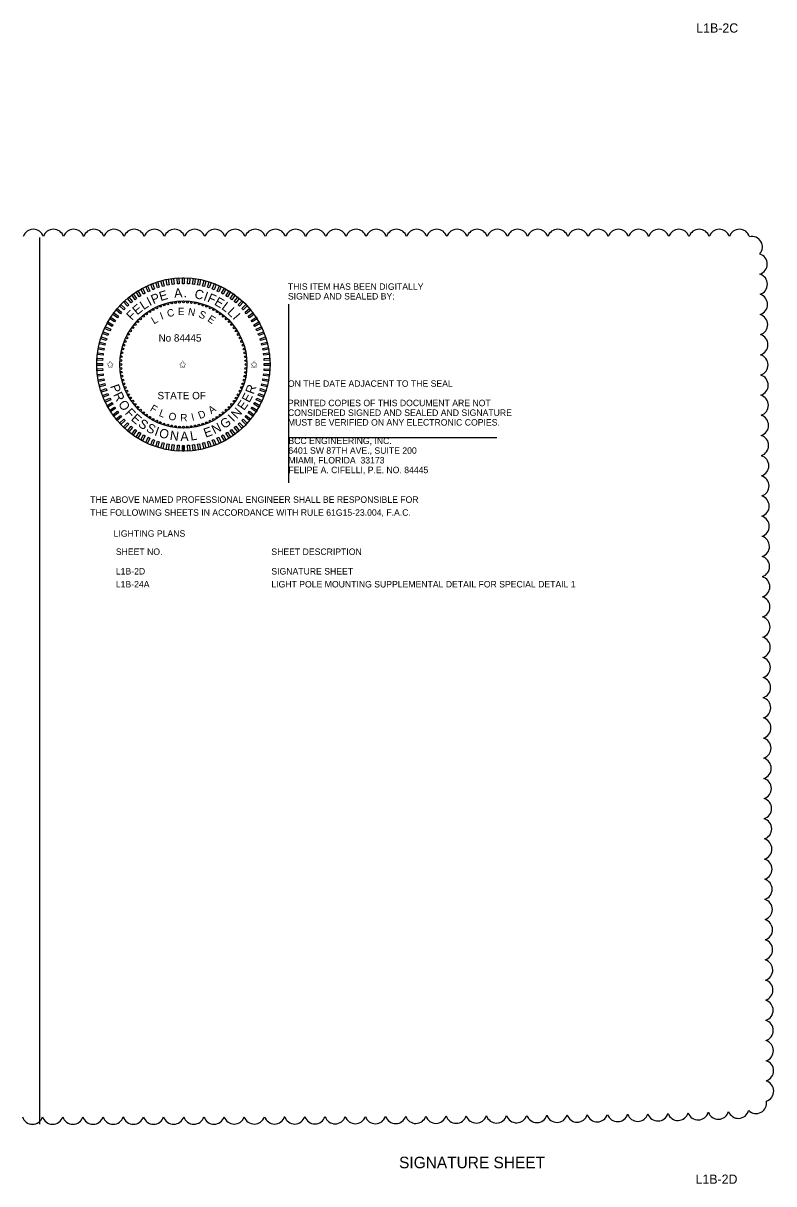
# Model space of a CAD drawing. Extents: x -811.2 to -795, y -2295.2 to -2235.1.
# Drawn here: x -803.27 to -795.14, y -2295.15 to -2282.59 of the extents above; entities that cross this region are included whole.
import ezdxf

# ---------------------------------------------------------------- set-up
doc = ezdxf.new("R2010")
doc.units = 0
for name, color, linetype in [('AdhocPoint_dp', 7, 'Continuous'), ('Cloud_dp', 7, 'Continuous'), ('PlotBorder_dp', 7, 'Continuous'), ('SheetLines_dp', 7, 'Continuous'), ('TextMinor', 7, 'Continuous'), ('TextMisc', 7, 'Continuous'), ('TextNotes', 7, 'Continuous'), ('TextShtNo', 7, 'Continuous')]:
    doc.layers.add(name, color=color, linetype=linetype)

msp = doc.modelspace()

# ---------------------------------------------------------------- linework, layer by layer
at = {"layer": 'AdhocPoint_dp'}
for p, q in [((-800.397, -2285.629), (-800.397, -2287.564)), ((-800.397, -2287.074), (-798.141, -2287.074))]:
    msp.add_line(p, q, dxfattribs=at)
at = {"layer": 'Cloud_dp'}
for centre, start, end in [((-803.157, -2284.933), 17.5, 162.5), ((-802.939, -2284.933), 17.5, 162.5), ((-802.721, -2284.933), 17.5, 162.5), ((-802.502, -2284.933), 17.5, 162.5), ((-802.284, -2284.933), 17.5, 162.5), ((-802.066, -2284.933), 17.5, 162.5), ((-801.847, -2284.933), 17.5, 162.5), ((-801.629, -2284.933), 17.5, 162.5), ((-801.411, -2284.933), 17.5, 162.5), ((-801.192, -2284.933), 17.5, 162.5), ((-800.974, -2284.933), 17.5, 162.5), ((-800.756, -2284.933), 17.5, 162.5), ((-800.537, -2284.933), 17.5, 162.5), ((-800.319, -2284.933), 17.5, 162.5), ((-800.101, -2284.933), 17.5, 162.5), ((-799.882, -2284.933), 17.5, 162.5), ((-799.664, -2284.933), 17.5, 162.5), ((-799.446, -2284.933), 17.5, 162.5), ((-799.227, -2284.933), 17.5, 162.5), ((-799.009, -2284.933), 17.5, 162.5), ((-798.791, -2284.933), 17.5, 162.5), ((-798.572, -2284.933), 17.5, 162.5), ((-798.354, -2284.933), 17.5, 162.5), ((-798.136, -2284.933), 17.5, 162.5), ((-797.917, -2284.933), 17.5, 162.5), ((-797.699, -2284.933), 17.5, 162.5), ((-797.481, -2284.933), 17.5, 162.5), ((-797.262, -2284.933), 17.5, 162.5), ((-797.044, -2284.933), 17.5, 162.5), ((-796.826, -2284.933), 17.5, 162.5), ((-796.607, -2284.933), 17.5, 162.5), ((-796.389, -2284.933), 17.5, 162.5), ((-796.171, -2284.933), 17.5, 162.5), ((-795.952, -2284.933), 17.5, 162.5), ((-795.734, -2284.933), 17.5, 162.5), ((-795.516, -2284.933), 17.5, 162.5), ((-795.381, -2285.01), 318.1116, 103.1116), ((-795.329, -2285.196), 287.9529, 72.9529), ((-795.327, -2285.414), 287.9529, 72.9529), ((-795.326, -2285.632), 287.9529, 72.9529), ((-795.324, -2285.851), 287.9529, 72.9529), ((-795.322, -2286.069), 287.9529, 72.9529), ((-795.32, -2286.287), 287.9529, 72.9529), ((-795.319, -2286.506), 287.9529, 72.9529), ((-795.317, -2286.724), 287.9529, 72.9529), ((-795.315, -2286.942), 287.9529, 72.9529), ((-795.314, -2287.16), 287.9529, 72.9529), ((-795.312, -2287.379), 287.9529, 72.9529), ((-795.31, -2287.597), 287.9529, 72.9529), ((-795.308, -2287.815), 287.9529, 72.9529), ((-795.307, -2288.034), 287.9529, 72.9529), ((-795.305, -2288.252), 287.9529, 72.9529), ((-795.303, -2288.47), 287.9529, 72.9529), ((-795.301, -2288.689), 287.9529, 72.9529), ((-795.3, -2288.907), 287.9529, 72.9529), ((-795.298, -2289.125), 287.9529, 72.9529), ((-795.296, -2289.344), 287.9529, 72.9529), ((-795.295, -2289.562), 287.9529, 72.9529), ((-795.293, -2289.78), 287.9527, 72.9527), ((-795.291, -2289.999), 287.9524, 72.9524), ((-795.289, -2290.217), 287.9521, 72.9521), ((-795.288, -2290.435), 287.9519, 72.9519), ((-795.286, -2290.654), 287.9515, 72.9515), ((-795.284, -2290.872), 287.9512, 72.9512), ((-795.282, -2291.09), 287.9508, 72.9508), ((-795.281, -2291.309), 287.9504, 72.9504), ((-795.279, -2291.527), 287.9499, 72.9499), ((-795.277, -2291.745), 287.9494, 72.9494), ((-795.276, -2291.963), 287.9488, 72.9488), ((-795.274, -2292.182), 287.9481, 72.9481), ((-795.272, -2292.4), 287.9473, 72.9473), ((-795.271, -2292.618), 287.9464, 72.9464), ((-795.269, -2292.837), 287.9452, 72.9452), ((-795.267, -2293.055), 287.9438, 72.9438), ((-795.265, -2293.273), 287.9419, 72.9419), ((-795.264, -2293.492), 287.9394, 72.9394), ((-795.262, -2293.71), 287.9355, 72.9355), ((-795.26, -2293.928), 287.9288, 72.9288), ((-795.259, -2294.147), 287.9106, 72.9106), ((-795.336, -2294.276), 225.4798, 10.4798), ((-803.166, -2294.393), 197.496, 342.496), ((-802.948, -2294.393), 197.5011, 342.5011), ((-802.729, -2294.393), 197.5111, 342.5111), ((-802.511, -2294.393), 197.522, 342.522), ((-802.293, -2294.393), 197.5335, 342.5335), ((-802.074, -2294.393), 197.5456, 342.5456), ((-801.856, -2294.393), 197.5582, 342.5582), ((-801.638, -2294.392), 197.5715, 342.5715), ((-801.42, -2294.392), 197.5855, 342.5855), ((-801.201, -2294.392), 197.6002, 342.6002), ((-800.983, -2294.391), 197.6157, 342.6157), ((-800.765, -2294.391), 197.6322, 342.6322), ((-800.546, -2294.39), 197.6497, 342.6497), ((-800.328, -2294.39), 197.6683, 342.6683), ((-800.11, -2294.389), 197.6881, 342.6881), ((-799.891, -2294.388), 197.7093, 342.7093), ((-799.673, -2294.387), 197.732, 342.732), ((-799.455, -2294.387), 197.7565, 342.7565), ((-799.236, -2294.386), 197.7829, 342.7829), ((-799.018, -2294.384), 197.8116, 342.8116), ((-798.8, -2294.383), 197.8429, 342.8429), ((-798.582, -2294.382), 197.8771, 342.8771), ((-798.363, -2294.38), 197.9149, 342.9149), ((-798.145, -2294.379), 197.9569, 342.9569), ((-797.927, -2294.377), 198.0039, 343.0039), ((-797.708, -2294.375), 198.0569, 343.0569), ((-797.49, -2294.373), 198.1174, 343.1174), ((-797.272, -2294.37), 198.1874, 343.1874), ((-797.054, -2294.367), 198.2696, 343.2696), ((-796.835, -2294.364), 198.368, 343.368), ((-796.617, -2294.361), 198.4888, 343.4888), ((-796.399, -2294.357), 198.642, 343.642), ((-796.181, -2294.352), 198.8454, 343.8454), ((-795.963, -2294.346), 199.1345, 344.1345), ((-795.745, -2294.339), 199.5943, 344.5943), ((-795.527, -2294.329), 200.5167, 345.5167)]:
    msp.add_arc(centre, 0.114, start, end, dxfattribs=at)
at = {"layer": 'TextMinor'}
for radius in [0.938, 0.688]:
    msp.add_circle((-801.533, -2286.283), radius, dxfattribs=at)
at = {"layer": 'TextNotes'}
msp.add_line((-803.086, -2294.507), (-803.086, -2284.907), dxfattribs=at)
at = {"layer": 'TextShtNo'}
for p, q in [((-801.543, -2287.22), (-801.543, -2287.158)), ((-801.533, -2287.22), (-801.533, -2287.158)), ((-801.523, -2287.22), (-801.523, -2287.158))]:
    msp.add_line(p, q, dxfattribs=at)
for points in [[(-801.794, -2285.447), (-801.813, -2285.454), (-801.832, -2285.394), (-801.813, -2285.388)], [(-801.741, -2285.433), (-801.76, -2285.438), (-801.776, -2285.377), (-801.756, -2285.372)], [(-801.687, -2285.421), (-801.707, -2285.425), (-801.718, -2285.364), (-801.699, -2285.36)], [(-801.632, -2285.413), (-801.653, -2285.416), (-801.66, -2285.354), (-801.64, -2285.351)], [(-801.578, -2285.409), (-801.598, -2285.41), (-801.602, -2285.348), (-801.582, -2285.346)], [(-801.523, -2285.408), (-801.543, -2285.408), (-801.543, -2285.345), (-801.523, -2285.345)], [(-801.468, -2285.41), (-801.488, -2285.409), (-801.484, -2285.346), (-801.464, -2285.348)], [(-801.413, -2285.416), (-801.433, -2285.413), (-801.425, -2285.351), (-801.405, -2285.354)], [(-801.359, -2285.425), (-801.379, -2285.421), (-801.367, -2285.36), (-801.347, -2285.364)], [(-801.305, -2285.438), (-801.325, -2285.433), (-801.309, -2285.372), (-801.29, -2285.377)], [(-801.253, -2285.454), (-801.272, -2285.447), (-801.253, -2285.388), (-801.234, -2285.394)], [(-802.039, -2285.569), (-802.055, -2285.581), (-802.092, -2285.53), (-802.076, -2285.518)], [(-801.993, -2285.538), (-802.01, -2285.549), (-802.044, -2285.497), (-802.027, -2285.486)], [(-801.946, -2285.511), (-801.963, -2285.521), (-801.993, -2285.466), (-801.976, -2285.456)], [(-801.896, -2285.487), (-801.915, -2285.495), (-801.941, -2285.439), (-801.923, -2285.43)], [(-801.846, -2285.465), (-801.864, -2285.473), (-801.887, -2285.415), (-801.869, -2285.407)], [(-801.201, -2285.473), (-801.22, -2285.465), (-801.197, -2285.407), (-801.178, -2285.415)], [(-801.151, -2285.495), (-801.169, -2285.487), (-801.143, -2285.43), (-801.125, -2285.439)], [(-801.102, -2285.521), (-801.12, -2285.511), (-801.09, -2285.456), (-801.072, -2285.466)], [(-801.055, -2285.549), (-801.073, -2285.539), (-801.039, -2285.486), (-801.022, -2285.497)], [(-801.01, -2285.581), (-801.027, -2285.569), (-800.99, -2285.518), (-800.974, -2285.53)], [(-802.164, -2285.676), (-802.178, -2285.691), (-802.223, -2285.648), (-802.209, -2285.634)], [(-802.124, -2285.638), (-802.139, -2285.652), (-802.182, -2285.606), (-802.167, -2285.592)], [(-802.083, -2285.602), (-802.098, -2285.615), (-802.138, -2285.567), (-802.123, -2285.554)], [(-800.967, -2285.615), (-800.983, -2285.602), (-800.943, -2285.554), (-800.928, -2285.567)], [(-800.926, -2285.652), (-800.941, -2285.638), (-800.898, -2285.592), (-800.884, -2285.606)], [(-800.888, -2285.691), (-800.902, -2285.676), (-800.856, -2285.634), (-800.843, -2285.648)], [(-802.266, -2285.805), (-802.277, -2285.822), (-802.33, -2285.789), (-802.319, -2285.772)], [(-802.235, -2285.76), (-802.247, -2285.776), (-802.297, -2285.74), (-802.285, -2285.723)], [(-802.201, -2285.717), (-802.214, -2285.733), (-802.262, -2285.693), (-802.249, -2285.677)], [(-800.852, -2285.733), (-800.865, -2285.717), (-800.817, -2285.677), (-800.804, -2285.693)], [(-800.819, -2285.777), (-800.831, -2285.76), (-800.78, -2285.724), (-800.769, -2285.74)], [(-800.789, -2285.822), (-800.799, -2285.805), (-800.747, -2285.772), (-800.736, -2285.789)], [(-802.32, -2285.901), (-802.329, -2285.919), (-802.385, -2285.893), (-802.377, -2285.874)], [(-802.295, -2285.852), (-802.305, -2285.87), (-802.359, -2285.84), (-802.35, -2285.822)], [(-800.761, -2285.87), (-800.771, -2285.852), (-800.716, -2285.822), (-800.707, -2285.84)], [(-800.737, -2285.919), (-800.745, -2285.901), (-800.689, -2285.875), (-800.68, -2285.893)], [(-802.362, -2286.003), (-802.368, -2286.022), (-802.428, -2286.003), (-802.421, -2285.983)], [(-802.343, -2285.951), (-802.35, -2285.97), (-802.408, -2285.947), (-802.401, -2285.928)], [(-800.716, -2285.97), (-800.723, -2285.951), (-800.665, -2285.928), (-800.658, -2285.947)], [(-800.698, -2286.022), (-800.704, -2286.003), (-800.644, -2285.984), (-800.638, -2286.003)], [(-802.4, -2286.163), (-802.402, -2286.183), (-802.464, -2286.175), (-802.462, -2286.155)], [(-802.391, -2286.109), (-802.394, -2286.129), (-802.456, -2286.117), (-802.452, -2286.097)], [(-802.378, -2286.055), (-802.383, -2286.075), (-802.443, -2286.059), (-802.438, -2286.04)], [(-800.683, -2286.075), (-800.688, -2286.055), (-800.627, -2286.04), (-800.622, -2286.059)], [(-800.671, -2286.129), (-800.675, -2286.109), (-800.614, -2286.097), (-800.61, -2286.117)], [(-800.664, -2286.183), (-800.666, -2286.163), (-800.604, -2286.155), (-800.602, -2286.175)], [(-802.408, -2286.273), (-802.408, -2286.293), (-802.47, -2286.293), (-802.47, -2286.273)], [(-802.406, -2286.218), (-802.407, -2286.238), (-802.469, -2286.234), (-802.468, -2286.214)], [(-800.659, -2286.238), (-800.66, -2286.218), (-800.598, -2286.214), (-800.597, -2286.234)], [(-800.658, -2286.293), (-800.658, -2286.273), (-800.595, -2286.273), (-800.595, -2286.293)], [(-802.407, -2286.327), (-802.406, -2286.348), (-802.468, -2286.352), (-802.469, -2286.331)], [(-802.402, -2286.382), (-802.4, -2286.402), (-802.462, -2286.41), (-802.464, -2286.39)], [(-800.666, -2286.402), (-800.664, -2286.382), (-800.602, -2286.39), (-800.604, -2286.41)], [(-800.66, -2286.348), (-800.659, -2286.328), (-800.597, -2286.332), (-800.598, -2286.352)], [(-802.394, -2286.437), (-802.391, -2286.456), (-802.452, -2286.468), (-802.456, -2286.448)], [(-802.383, -2286.49), (-802.378, -2286.51), (-802.438, -2286.526), (-802.443, -2286.506)], [(-800.688, -2286.51), (-800.683, -2286.491), (-800.622, -2286.506), (-800.627, -2286.526)], [(-800.675, -2286.457), (-800.672, -2286.437), (-800.61, -2286.449), (-800.614, -2286.468)], [(-802.368, -2286.543), (-802.362, -2286.563), (-802.421, -2286.582), (-802.428, -2286.563)], [(-802.35, -2286.595), (-802.343, -2286.614), (-802.401, -2286.637), (-802.408, -2286.618)], [(-802.329, -2286.646), (-802.32, -2286.664), (-802.377, -2286.691), (-802.386, -2286.673)], [(-800.746, -2286.664), (-800.737, -2286.646), (-800.68, -2286.673), (-800.689, -2286.691)], [(-800.723, -2286.614), (-800.716, -2286.596), (-800.658, -2286.619), (-800.665, -2286.637)], [(-800.704, -2286.563), (-800.698, -2286.544), (-800.638, -2286.563), (-800.644, -2286.582)], [(-802.305, -2286.695), (-802.295, -2286.713), (-802.35, -2286.743), (-802.359, -2286.725)], [(-802.277, -2286.743), (-802.266, -2286.76), (-802.319, -2286.793), (-802.33, -2286.776)], [(-800.8, -2286.76), (-800.789, -2286.743), (-800.736, -2286.777), (-800.747, -2286.794)], [(-800.771, -2286.713), (-800.761, -2286.695), (-800.707, -2286.726), (-800.716, -2286.743)], [(-802.247, -2286.789), (-802.235, -2286.805), (-802.285, -2286.842), (-802.297, -2286.826)], [(-802.214, -2286.833), (-802.201, -2286.848), (-802.249, -2286.888), (-802.262, -2286.872)], [(-802.178, -2286.874), (-802.164, -2286.889), (-802.209, -2286.932), (-802.223, -2286.917)], [(-800.902, -2286.889), (-800.888, -2286.874), (-800.843, -2286.917), (-800.857, -2286.932)], [(-800.865, -2286.848), (-800.852, -2286.833), (-800.804, -2286.873), (-800.817, -2286.888)], [(-800.831, -2286.805), (-800.819, -2286.789), (-800.769, -2286.826), (-800.78, -2286.842)], [(-802.139, -2286.914), (-802.125, -2286.927), (-802.167, -2286.973), (-802.182, -2286.959)], [(-802.099, -2286.95), (-802.083, -2286.963), (-802.123, -2287.011), (-802.138, -2286.999)], [(-802.055, -2286.985), (-802.039, -2286.997), (-802.076, -2287.047), (-802.092, -2287.035)], [(-802.01, -2287.016), (-801.993, -2287.027), (-802.027, -2287.08), (-802.044, -2287.069)], [(-801.073, -2287.027), (-801.056, -2287.016), (-801.022, -2287.069), (-801.039, -2287.08)], [(-801.027, -2286.997), (-801.011, -2286.985), (-800.974, -2287.035), (-800.99, -2287.047)], [(-800.983, -2286.963), (-800.967, -2286.951), (-800.928, -2286.999), (-800.943, -2287.012)], [(-800.941, -2286.928), (-800.927, -2286.914), (-800.884, -2286.959), (-800.899, -2286.973)], [(-801.963, -2287.045), (-801.946, -2287.054), (-801.976, -2287.109), (-801.993, -2287.099)], [(-801.915, -2287.07), (-801.896, -2287.079), (-801.923, -2287.135), (-801.941, -2287.127)], [(-801.865, -2287.093), (-801.846, -2287.1), (-801.869, -2287.158), (-801.887, -2287.151)], [(-801.813, -2287.112), (-801.794, -2287.118), (-801.813, -2287.177), (-801.832, -2287.171)], [(-801.76, -2287.128), (-801.741, -2287.133), (-801.756, -2287.193), (-801.776, -2287.188)], [(-801.707, -2287.14), (-801.687, -2287.144), (-801.699, -2287.205), (-801.719, -2287.202)], [(-801.653, -2287.15), (-801.633, -2287.152), (-801.64, -2287.214), (-801.661, -2287.212)], [(-801.598, -2287.155), (-801.578, -2287.157), (-801.582, -2287.219), (-801.602, -2287.218)], [(-801.543, -2287.158), (-801.523, -2287.158), (-801.523, -2287.22), (-801.543, -2287.22)], [(-801.488, -2287.157), (-801.468, -2287.155), (-801.464, -2287.218), (-801.484, -2287.219)], [(-801.433, -2287.152), (-801.413, -2287.15), (-801.406, -2287.212), (-801.426, -2287.214)], [(-801.379, -2287.144), (-801.359, -2287.14), (-801.347, -2287.202), (-801.367, -2287.205)], [(-801.325, -2287.133), (-801.306, -2287.128), (-801.29, -2287.188), (-801.31, -2287.193)], [(-801.272, -2287.118), (-801.253, -2287.112), (-801.234, -2287.171), (-801.253, -2287.177)], [(-801.22, -2287.1), (-801.202, -2287.093), (-801.179, -2287.151), (-801.197, -2287.158)], [(-801.17, -2287.079), (-801.151, -2287.07), (-801.125, -2287.127), (-801.143, -2287.135)], [(-801.12, -2287.054), (-801.103, -2287.045), (-801.073, -2287.099), (-801.09, -2287.109)]]:
    msp.add_lwpolyline(points, close=True, dxfattribs=at)
for centre in [(-801.782, -2285.653), (-801.742, -2285.638), (-801.701, -2285.626), (-801.659, -2285.617), (-801.617, -2285.611), (-801.575, -2285.607), (-801.532, -2285.605), (-801.49, -2285.607), (-801.447, -2285.611), (-801.405, -2285.617), (-801.364, -2285.627), (-801.323, -2285.639), (-801.283, -2285.653), (-801.996, -2285.788), (-801.964, -2285.76), (-801.931, -2285.734), (-801.895, -2285.71), (-801.859, -2285.689), (-801.821, -2285.669), (-801.244, -2285.67), (-801.206, -2285.689), (-801.169, -2285.711), (-801.134, -2285.735), (-801.101, -2285.761), (-801.069, -2285.789), (-802.081, -2285.884), (-802.055, -2285.85), (-802.026, -2285.819), (-801.039, -2285.819), (-801.011, -2285.851), (-800.985, -2285.885), (-802.163, -2286.033), (-802.146, -2285.994), (-802.126, -2285.956), (-802.105, -2285.919), (-800.961, -2285.92), (-800.939, -2285.957), (-800.92, -2285.995), (-800.903, -2286.034), (-802.198, -2286.155), (-802.189, -2286.114), (-802.177, -2286.073), (-800.888, -2286.074), (-800.877, -2286.115), (-800.867, -2286.156), (-802.21, -2286.282), (-802.209, -2286.24), (-802.205, -2286.197), (-800.861, -2286.198), (-800.857, -2286.241), (-800.855, -2286.283), (-802.209, -2286.325), (-802.205, -2286.367), (-802.198, -2286.409), (-800.868, -2286.41), (-800.861, -2286.368), (-800.857, -2286.326), (-802.189, -2286.451), (-802.177, -2286.492), (-802.163, -2286.532), (-800.903, -2286.533), (-800.889, -2286.493), (-800.877, -2286.452), (-802.146, -2286.571), (-802.127, -2286.609), (-802.105, -2286.645), (-800.961, -2286.646), (-800.94, -2286.61), (-800.92, -2286.572), (-802.081, -2286.68), (-802.055, -2286.714), (-802.027, -2286.746), (-801.997, -2286.776), (-801.07, -2286.777), (-801.039, -2286.747), (-801.011, -2286.715), (-800.985, -2286.681), (-801.965, -2286.804), (-801.932, -2286.83), (-801.896, -2286.854), (-801.86, -2286.876), (-801.822, -2286.895), (-801.783, -2286.912), (-801.284, -2286.913), (-801.245, -2286.896), (-801.207, -2286.877), (-801.17, -2286.855), (-801.135, -2286.831), (-801.102, -2286.805), (-801.743, -2286.927), (-801.702, -2286.939), (-801.66, -2286.948), (-801.618, -2286.955), (-801.576, -2286.959), (-801.533, -2286.96), (-801.491, -2286.959), (-801.449, -2286.955), (-801.407, -2286.948), (-801.365, -2286.939), (-801.324, -2286.927)]:
    msp.add_circle(centre, 0.01, dxfattribs=at)

# ---------------------------------------------------------------- texts
at = {"layer": 'PlotBorder_dp'}
for s, height, p in [('THIS ITEM HAS BEEN DIGITALLY', 0.07, (-800.402, -2285.474)), ('SIGNED AND SEALED BY:', 0.07, (-800.402, -2285.579)), ('ON THE DATE ADJACENT TO THE SEAL', 0.07, (-800.402, -2286.524)), ('CONSIDERED SIGNED AND SEALED AND SIGNATURE ', 0.07, (-800.402, -2286.839)), ('PRINTED COPIES OF THIS DOCUMENT ARE NOT ', 0.07, (-800.402, -2286.734)), ('MUST BE VERIFIED ON ANY ELECTRONIC COPIES.', 0.07, (-800.402, -2286.944)), ('BCC ENGINEERING, INC.', 0.07, (-800.397, -2287.144)), ('6401 SW 87TH AVE., SUITE 200', 0.07, (-800.397, -2287.249)), ('MIAMI, FLORIDA  33173', 0.07, (-800.397, -2287.354)), ('FELIPE A. CIFELLI, P.E. NO. 84445', 0.07, (-800.397, -2287.459)), ('THE ABOVE NAMED PROFESSIONAL ENGINEER SHALL BE RESPONSIBLE FOR ', 0.07, (-802.541, -2287.78)), ('THE FOLLOWING SHEETS IN ACCORDANCE WITH RULE 61G15-23.004, F.A.C.', 0.07, (-802.541, -2287.92)), ('LIGHTING PLANS', 0.07, (-802.288, -2288.147)), ('       SIGNATURE SHEET         ', 0.125, (-799.524, -2294.983))]:
    msp.add_text(s, height=height, dxfattribs=at).set_placement(p)
at = {"layer": 'SheetLines_dp'}
for s, p in [('L1B-2C ', (-795.983, -2282.69)), ('L1B-2D ', (-795.991, -2295.151))]:
    msp.add_text(s, height=0.1, dxfattribs=at).set_placement(p)
at = {"layer": 'TextMisc'}
for s, p in [('SHEET NO.', (-802.264, -2288.344)), ('SHEET DESCRIPTION', (-800.581, -2288.344)), ('L1B-2D', (-802.264, -2288.556)), ('SIGNATURE SHEET', (-800.581, -2288.556)), ('L1B-24A', (-802.264, -2288.696)), ('LIGHT POLE MOUNTING SUPPLEMENTAL DETAIL FOR SPECIAL DETAIL 1', (-800.581, -2288.696))]:
    msp.add_text(s, height=0.07, dxfattribs=at).set_placement(p)
at = {"layer": 'TextShtNo'}
for s, height, rotation, p in [('P', 0.1, 23.2829, (-801.858, -2285.631)), ('E', 0.1, 16.5426, (-801.779, -2285.597)), ('A', 0.1, 4.421, (-801.63, -2285.561)), ('C', 0.1, 347.7999, (-801.419, -2285.563)), ('I', 0.1, 340.0631, (-801.323, -2285.585)), ('F', 0.1, 336.5299, (-801.281, -2285.599)), ('E', 0.1, 40.1214, (-802.033, -2285.753)), ('L', 0.1, 33.0792, (-801.964, -2285.695)), ('I', 0.1, 26.8161, (-801.898, -2285.652)), ('.', 0.1, 356.654, (-801.531, -2285.554)), ('E', 0.1, 330.0796, (-801.206, -2285.632)), ('L', 0.1, 323.0373, (-801.128, -2285.677)), ('F', 0.1, 46.5718, (-802.089, -2285.812)), ('L', 0.08, 30.4021, (-801.852, -2285.849)), ('I', 0.08, 20.0117, (-801.769, -2285.799)), ('C', 0.08, 12.2025, (-801.701, -2285.771)), ('E', 0.08, 0.4186, (-801.593, -2285.748)), ('N', 0.08, 349.2914, (-801.488, -2285.746)), ('S', 0.08, 337.0221, (-801.375, -2285.768)), ('E', 0.08, 325.8663, (-801.279, -2285.808)), ('L', 0.1, 316.7742, (-801.065, -2285.725)), ('I', 0.1, 310.5111, (-801.006, -2285.779)), ('P', 0.1, 289.4055, (-802.328, -2286.517)), ('R', 0.1, 69.5134, (-800.773, -2286.612)), ('R', 0.1, 296.1458, (-802.295, -2286.609)), ('E', 0.1, 62.4712, (-800.819, -2286.703)), ('O', 0.1, 303.9671, (-802.243, -2286.71)), ('F', 0.1, 312.628, (-802.171, -2286.812)), ('F', 0.08, 328.7241, (-801.901, -2286.779)), ('L', 0.08, 339.2916, (-801.804, -2286.838)), ('D', 0.08, 22.0128, (-801.355, -2286.875)), ('A', 0.08, 34.4992, (-801.231, -2286.822)), ('N', 0.1, 47.1788, (-800.955, -2286.877)), ('E', 0.1, 55.4289, (-800.876, -2286.787)), ('E', 0.1, 319.0783, (-802.107, -2286.88)), ('S', 0.1, 326.1206, (-802.03, -2286.946)), ('O', 0.08, 349.6821, (-801.699, -2286.878)), ('R', 0.08, 2.3398, (-801.565, -2286.9)), ('I', 0.08, 14.2037, (-801.437, -2286.893)), ('N', 0.1, 26.8614, (-801.197, -2287.04)), ('G', 0.1, 35.1115, (-801.092, -2286.984)), ('I', 0.1, 43.6456, (-800.993, -2286.911)), ('S', 0.1, 333.193, (-801.944, -2287.002)), ('I', 0.1, 340.2654, (-801.853, -2287.047)), ('O', 0.1, 343.7986, (-801.805, -2287.065)), ('N', 0.1, 352.4595, (-801.684, -2287.097)), ('A', 0.1, 0.7097, (-801.565, -2287.111)), ('L', 0.1, 8.4767, (-801.453, -2287.107)), ('E', 0.1, 19.8191, (-801.293, -2287.076))]:
    msp.add_text(s, height=height, rotation=rotation, dxfattribs=at).set_placement(p)
for s, p in [('No 84445', (-801.802, -2286.035)), ('✩', (-802.368, -2286.321)), ('✩', (-801.583, -2286.321)), ('✩', (-800.811, -2286.321)), ('STATE OF', (-801.813, -2286.659))]:
    msp.add_text(s, height=0.08, dxfattribs=at).set_placement(p)

doc.saveas('drawing.dxf')
